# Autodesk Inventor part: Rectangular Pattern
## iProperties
Shininess: 64.0
Length Units: 11269
Angle Units: 11279
Time Units: 11290
Mass Units: 11283
Length Display Precision: 3
Angle Display Precision: 2
Compacted: True
Part Number: Rectangular Pattern
Document SubType Name: Modeling
Created: 2002-12
Designer: deepak
Density: 1 g/cm^3
Density: 0.0
Volumn: 0.0
Area: 0.0
PropertySet Name: Model Information
Control State: 0
Master: False
Checked Out: False
Author: deepak
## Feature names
1. Extrusion1
2. Extrusion2
3. Extrusion3
4. Extrusion4
5. Rectangular Pattern1
